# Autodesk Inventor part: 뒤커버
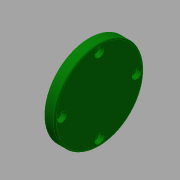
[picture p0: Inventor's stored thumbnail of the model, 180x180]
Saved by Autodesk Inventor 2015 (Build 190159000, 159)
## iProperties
Created: 2015-09
Part Number: 뒤커버
Material: 알루미늄 6061
Document SubType Name: Modeling
Designer: mduedu
Density: 2.71 g/cm^3
Mass: 54.0417 g
Surface Area: 84.9688 cm^2
Volume: 19.9416 cm^3
Appearance: 진녹색
Author: mduedu
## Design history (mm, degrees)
sketch "스케치1"
  geometry: L1 (-15.5, 47)-(-15.5, 78); L2 (-15.5, 78)-(-22.5, 78); L3 (-22.5, 78)-(-22.5, 63); L4 (-28.5, 63)-(-28.5, 47); L5 (-79.5, 39.5)-(-79.5, 54.5) reference; L6 (48.5, 54.5)-(48.5, 39.5) reference; L7 (-79.5, 47)-(48.5, 47); L8 (-22.5, 63)-(-28.5, 63); L9 (-28.5, 47)-(-15.5, 47); 1 further point
  constraints: 14 end point, 4 midpoint, 3 parallel, 1 collinear, 1 point on line, 1 vertical
  dimensions: "d6" = 62 diameter of L2 L7; "d7" = 7 distance of L1.end L2.end; "d8" = 32 diameter of L3.end L7; "d32" = 13 distance between parallel lines of L1 L4
revolve "회전1" sketch "스케치1" stored, may be unused: angle "d4" = 90 deg
sketch "스케치4"
  geometry: C1 r 31 at (0, 0) reference; 2 further points
  constraints: 1 coincident
hole "구멍3" sketch "스케치4" at (0, 0) diameter "d33" = 22; stored, may be unused: countersink angle "d37" = 90 deg, drill point angle "d39" = 0 deg; dims "d34" = 6, "d35" = 4, "d36" = 2, "d38" = 8
fillet "모깎기4" dims "d40" = 1
chamfer "모따기2" distance "d41" = 1; stored, may be unused: second distance "d42" = 2, angle "d43" = 45 deg
sketch "스케치6" dims "d56" = 52
  geometry: C1 r 31 at (0, 0) reference; 5 further points
  constraints: 2 vertical alignment, 1 coincident, 7 other
  dimensions: "d59" = 360 deg dimension on C1.centre point (0, 26) (derived)
hole "구멍4" sketch "스케치6" at (0, 26), (-26, 0), (0, -26), (26, 0) diameter "d49" = 3.4; stored, may be unused: countersink angle "d53" = 90 deg, drill point angle "d55" = 0 deg; dims "d50" = 6, "d51" = 6.5, "d52" = 3.4, "d54" = 8
fillet "모깎기5" dims "d61" = 3
node "솔리드1"
node "참조1"
node "참조2"
